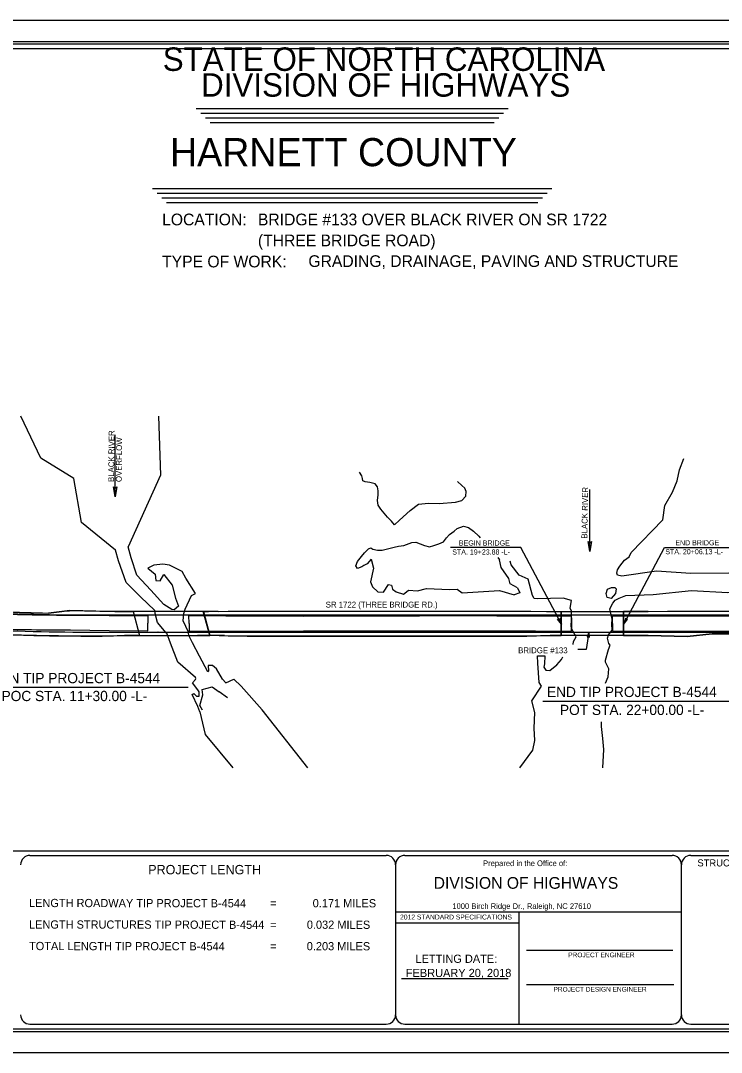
# Model space of a CAD drawing. Extents: x 0 to 2021, y 0 to 1321.
# Drawn here: x 675 to 1572, y 0 to 1321 of the extents above; entities that cross this region are included whole.
import ezdxf

# ---------------------------------------------------------------- set-up
doc = ezdxf.new("R2010")
doc.units = 0
for name, color, linetype in [('Arrowhead Terminators CELL', 7, 'Continuous'), ('Default', 7, 'Continuous'), ('Dimension Lines', 7, 'Continuous'), ('Exist Hydro Stream or Body of Water', 7, 'Continuous'), ('Exist Roads EOP', 7, 'Continuous'), ('Prop EOT', 7, 'Continuous'), ('Sheet Data Field CELL', 7, 'Continuous'), ('Sheet Plot Border Inside CELL', 7, 'Continuous'), ('Sheet Plot Border Outside CELL', 7, 'Continuous'), ('Sheet Title CELL', 7, 'Continuous'), ('Text', 7, 'Continuous')]:
    doc.layers.add(name, color=color, linetype=linetype)

msp = doc.modelspace()

# ---------------------------------------------------------------- linework, layer by layer
at = {"layer": 'Arrowhead Terminators CELL'}
for points in [[(850.5, 537.9), (850.4, 537.9), (850.5, 537.9)], [(850.5, 537.9), (850.4, 537.8), (850.5, 537.8)], [(1402.2, 537.9), (1399.8, 532), (1402.8, 531.5)]]:
    msp.add_lwpolyline(points, close=True, dxfattribs=at)
at = {"layer": 'Default'}
for p, q in [((795.7, 711.1), (795.7, 790.4)), ((1403.5, 641.2), (1403.5, 720.4)), ((737.4, 565.4), (710.2, 562.3)), ((737.3, 565.4), (795.1, 564.4)), ((787.3, 564.4), (737.4, 565.4)), ((818.6, 564.4), (787.3, 564.4)), ((795.1, 564.4), (818.5, 564.4)), ((818.5, 564.4), (826.8, 533.5)), ((818.5, 564.4), (826.8, 533.5)), ((908.5, 564.4), (818.5, 564.4)), ((916.7, 533.5), (908.4, 564.4)), ((908.4, 564.4), (915.3, 564.4)), ((927.3, 564.4), (908.4, 564.4)), ((908.5, 564.4), (916.8, 533.5)), ((915.3, 564.4), (940.3, 564.9)), ((927.3, 564.4), (956.4, 564.9)), ((940.3, 564.9), (1327.8, 564.9)), ((956.4, 564.9), (1322.9, 564.9)), ((1322.9, 564.9), (1347.9, 564.4)), ((1327.8, 564.9), (1352.8, 564.4)), ((1347.9, 564.4), (1366.7, 564.4)), ((1352.8, 564.4), (1366.6, 564.4)), ((1366.6, 564.4), (1366.6, 533.5)), ((1366.6, 564.4), (1366.6, 533.5)), ((1477.9, 564.4), (1446.5, 564.4)), ((1446.6, 533.5), (1446.6, 564.4)), ((1446.6, 564.4), (1477.9, 564.4)), ((1477.9, 564.4), (1502.9, 564.9)), ((1477.9, 564.4), (1502.9, 564.9)), ((1502.9, 564.9), (1613.5, 564.9)), ((1502.9, 564.9), (1613.5, 564.9)), ((751.5, 532.9), (778.8, 532.9)), ((778.8, 532.9), (808, 533.5)), ((826.8, 533.5), (807.6, 533.5)), ((808, 533.5), (826.9, 533.5)), ((826.8, 533.5), (916.8, 533.5)), ((919.7, 533.5), (900.9, 533.5)), ((935.5, 533.5), (908.4, 533.5)), ((940.3, 532.9), (916.7, 533.5)), ((916.7, 533.5), (916.7, 533.5)), ((935.5, 533.5), (964.7, 532.9)), ((1327.8, 532.9), (940.3, 532.9)), ((964.7, 532.9), (1322.9, 532.9)), ((1322.9, 532.9), (1347.9, 533.5)), ((1352.8, 533.5), (1327.8, 532.9)), ((1347.9, 533.5), (1366.7, 533.5)), ((1366.6, 533.5), (1352.8, 533.5)), ((1446.5, 533.5), (1477.9, 533.5)), ((1477.9, 533.5), (1446.6, 533.5)), ((1527.9, 532.5), (1477.9, 533.5)), ((1477.9, 533.5), (1527.9, 532.5)), ((1559.9, 535.9), (1527.9, 532.5)), ((1527.9, 532.5), (1559.9, 535.9)), ((1641.6, 535.9), (1559.9, 535.9)), ((1559.9, 535.9), (1641.6, 535.9))]:
    msp.add_line(p, q, dxfattribs=at)
for points in [[(797.9, 723.7), (795.7, 711.1), (793.5, 723.8), (795.7, 722.2)], [(1405.7, 653.8), (1403.5, 641.2), (1401.3, 653.9), (1403.5, 652.3)], [(1364.5, 555.6), (1367, 547.9), (1362, 554.3), (1363.7, 554.1)], [(1449.3, 555.6), (1446.8, 547.9), (1451.8, 554.3), (1450.1, 554.1)]]:
    msp.add_lwpolyline(points, close=True, dxfattribs=at)
for centre, radius, start, end in [((733.6, 2481.6), 1919.4, 265.7307, 269.2997), ((751.5, 2891), 2329, 266.0471, 268.9838), ((-31.9, 7212.3), 6691.3, 276.36675, 276.6009), ((751.5, 2891), 2358, 267.4051, 270), ((760.5, 3797.9), 3264.7, 268.1837, 270.8273)]:
    msp.add_arc(centre, radius, start, end, dxfattribs=at)
at = {"layer": 'Dimension Lines'}
for p, q in [((1314.9, 646.3), (1225.1, 646.3)), ((1367, 547.9), (1314.9, 646.3)), ((1446.8, 547.9), (1498.9, 646.3)), ((1498.9, 646.3), (1581.8, 646.3)), ((1402.2, 537.9), (1398.8, 515.7)), ((1398.8, 515.7), (1388.2, 515.7)), ((889.2, 467.2), (610.1, 467.1)), ((1608.3, 449.3), (1343, 449.3))]:
    msp.add_line(p, q, dxfattribs=at)
at = {"layer": 'Exist Hydro Stream or Body of Water'}
msp.add_line((939.4, 453.7), (928.8, 461.4), dxfattribs=at)
for points in [[(796.1, 642.8), (752.5, 678.1), (742.6, 734.4), (700.4, 760.6), (674.8, 814.4)], [(851, 814.4), (853.8, 738.9), (812.4, 647)], [(1456.1, 639.7), (1496.7, 681.5), (1499.6, 700.1), (1509.4, 717), (1515.3, 731.6), (1518.4, 745.6), (1523.7, 760)], [(1153.3, 675.1), (1149.5, 679.8), (1144.5, 685), (1139.9, 690.3), (1135.8, 695.5), (1132.5, 700.6), (1131.5, 706.3), (1132.2, 713.5), (1132.3, 718.7), (1131.3, 724), (1128.4, 727.8), (1121.8, 729.4), (1115.9, 730.4), (1112.6, 731.4), (1112.1, 734.6), (1111.6, 738.1), (1108.5, 742.6)], [(1153.3, 675.1), (1159.7, 681.3), (1173.2, 693.8), (1183.9, 701.7), (1196.6, 702.8), (1210.6, 702.7), (1231.4, 704.4), (1239.6, 706.4), (1244.8, 711.9), (1245.2, 717.8), (1243.2, 722.1), (1239.4, 725.5), (1233.8, 730.8)], [(1153, 646.5), (1158.2, 648.1), (1165, 648.8), (1175.3, 652.6), (1180.4, 653.1), (1186.1, 651.1), (1191.7, 648.9), (1198.1, 647.3), (1203.8, 648.6), (1209.9, 651), (1215.8, 653.7), (1219.7, 658.8), (1223.8, 662.9), (1229.6, 667.2), (1233.3, 670.6), (1241.7, 673.5), (1248, 672), (1254.6, 667.2), (1261.3, 660.9), (1263, 658.7)], [(901.4, 464.1), (894.5, 472.8), (898.3, 477.3), (898.7, 478.7), (898.5, 480), (876, 499.6), (866.6, 523.8), (861.8, 536.7), (860.7, 536.8), (849.8, 550.1), (846.9, 561.6), (846.4, 565.6), (828, 583.3), (809.5, 601.6), (799.8, 629), (796.1, 642.8)], [(933, 477.5), (925.3, 490.8), (920.2, 495.3), (914.6, 495), (915.3, 487.9), (914.2, 487.1), (903.4, 507), (894.6, 524.3), (890.5, 532.6), (889.7, 532.7), (889.6, 537.7), (882.8, 552.4), (883.3, 561.9), (885.4, 567.2), (893.2, 584.8), (898.3, 587.5), (886.1, 607), (881.5, 615.6), (865, 623.5), (856.7, 624.7), (845, 623.8), (837.5, 619.6), (846.7, 611.9), (847.8, 603.9), (853, 603.4), (858.1, 611.5), (868.7, 598), (873, 581.2), (876.8, 571.1), (871.3, 566.3), (868.3, 566.8), (858.1, 573.4), (841.3, 591.5), (823.5, 610.7), (816.1, 633), (812.4, 647)], [(1123.3, 631.5), (1118.1, 625.4), (1114.1, 623.3), (1111.3, 621.7), (1105.9, 619.5), (1103.8, 622.7), (1105.8, 628.5), (1110.9, 634.8), (1114.9, 639.2), (1120.1, 644.5), (1123.1, 645.6), (1125.5, 644), (1131.3, 642.8), (1137.6, 642.9), (1140.9, 643.7), (1153, 646.5)], [(1429, 567.6), (1432.9, 575), (1436, 578.9), (1440.9, 581.2), (1449.4, 584.6), (1484.6, 586.2), (1533.6, 591.4), (1580.2, 588.6), (1635.2, 593.2), (1676.5, 589.5), (1680.5, 586.7), (1684, 583.8), (1733, 580.8), (1774.3, 583), (1774.8, 584.4), (1773.2, 593), (1775.8, 594.6), (1772.2, 601.2), (1772.2, 604.6), (1776.1, 613.6), (1836.6, 639), (1842.3, 644.3)], [(1636.7, 612.3), (1580.5, 613.2), (1532.6, 613), (1488.7, 616.1), (1444.2, 609.6), (1438.9, 610.9), (1437.9, 613.4), (1439, 617.7), (1441.7, 622.4), (1447.6, 630.2), (1453.7, 634.4), (1456.1, 639.7)], [(1123.3, 631.5), (1126.4, 619.7), (1122.5, 602.4), (1125.2, 595.9), (1131.9, 589.6), (1139.1, 589.2), (1145.5, 598.7), (1149.5, 598), (1150.5, 592.7), (1155.3, 589.7), (1164.6, 586.4), (1168.6, 589.4), (1171.2, 591.7), (1182.8, 590.9), (1194.3, 593.9), (1223.6, 592.6), (1233.6, 592.9), (1239.8, 588.3), (1287.8, 591), (1306.6, 585.8)], [(1285.6, 633.5), (1287.9, 630.5)], [(1310.9, 594.8), (1301.2, 599.6), (1299.7, 606.7), (1289.9, 620.8), (1287.9, 630.5)], [(1382.6, 525.9), (1386, 531.8), (1380.2, 541.8), (1380.2, 547.9), (1380.1, 564.9), (1379.7, 564.8), (1378.1, 568.5), (1379.8, 578.6), (1369.3, 581.5), (1336.6, 580.6), (1332, 581), (1330, 584.9), (1324.5, 605.9), (1312.7, 610.9), (1302.7, 623.9), (1301.2, 628.8)], [(1310.9, 594.8), (1313.6, 588.2), (1306.6, 585.8)], [(1431.1, 595), (1435.5, 595.2), (1437.3, 593.5), (1436.2, 587.2), (1430.7, 581), (1425.7, 582.3), (1424.1, 587.2), (1426, 592.7), (1431.1, 595)], [(1427.2, 534.3), (1431.8, 540.4), (1431.7, 548), (1431.8, 554.3), (1429, 567.6)], [(1432.3, 559.6), (1432.3, 559.6)], [(1423.3, 472.6), (1427, 480.9), (1427.9, 490.9), (1423.3, 499.5), (1423.3, 502.1), (1427.4, 515.6), (1429.5, 521.1), (1427.7, 523.4), (1425.9, 530.1), (1427.2, 534.3)], [(1381.9, 521.9), (1382.6, 525.9)], [(1341.6, 468.7), (1338.5, 473.6), (1337, 498), (1336.4, 507.6), (1345.6, 507.4), (1345.2, 497.3), (1344.6, 492.9), (1347.1, 489.4), (1352, 488.6), (1361.2, 496), (1367.3, 502.8), (1368.7, 506.4)], [(933, 477.5), (937.2, 473), (947.6, 477.8), (957, 468.7)], [(904, 435.8), (901.3, 442.8), (894.1, 458.1), (896.5, 459.2), (899.9, 455.8), (903.3, 455.8), (903.3, 461.6), (901.4, 464.1)], [(907.3, 437.9), (903.9, 443.8), (907.7, 457.6), (906.8, 464.3), (920, 468.1), (928.8, 461.4)], [(1042.2, 364.4), (984, 438.3), (957, 468.7)], [(1330.2, 387), (1333.1, 399.3), (1332.3, 414.9), (1333.1, 435.2), (1329.1, 449.8), (1341.6, 468.7)], [(904, 435.8), (910.9, 406.8), (946.2, 364.4)], [(1418, 423.2), (1418.1, 416.9), (1419.7, 401.8), (1420.8, 387.8), (1419.7, 364.4)], [(1313.7, 364.4), (1330.2, 387)]]:
    msp.add_lwpolyline(points, dxfattribs=at)
at = {"layer": 'Exist Roads EOP'}
for points in [[(739.1, 559.7), (739.1, 559.7), (788, 559.4), (837.2, 559.4), (837.4, 549.5)], [(890.2, 549.1), (890.1, 559.1), (937.1, 558.7), (986.9, 558.7), (1036.8, 558.5), (1086.3, 558.7), (1135.8, 558.8), (1185.4, 558.9), (1235.2, 559), (1284.5, 558.8), (1334.1, 558.6), (1379.6, 558.7), (1379.6, 549.2)], [(890.2, 549.1), (890.1, 559.1), (937.1, 558.7), (986.9, 558.7), (1036.8, 558.5), (1086.3, 558.7), (1135.8, 558.8), (1185.4, 558.9), (1235.2, 559), (1284.5, 558.8), (1334.1, 558.6), (1379.6, 558.7), (1379.6, 549.2)], [(1432.3, 549), (1432.3, 558.5), (1483.3, 558.8), (1532.5, 558.6), (1582.3, 558.5), (1632.3, 558.5), (1681.9, 558.6), (1731.9, 558.3), (1780.9, 558.3), (1831, 558.5), (1880.4, 558.8), (1894, 558.8)], [(738.2, 540.8), (738.2, 540.8), (787.7, 540.1), (837.5, 539.5), (837.4, 549.5)], [(890.2, 549.1), (890.3, 539.3), (937.3, 539.1), (987.3, 539.2), (1036.7, 539.5), (1086.3, 539.6), (1135.6, 539.7), (1185.3, 539.6), (1234.8, 539.7), (1284.1, 539.6), (1333.9, 539.4), (1379.7, 539), (1379.6, 549.2)], [(1432.3, 549), (1432.2, 539.3), (1483, 539.2), (1532.5, 539), (1582.6, 539.1), (1632.1, 539.3), (1681.7, 539.5), (1731.7, 539.5), (1781.1, 539.4), (1830.8, 539.3), (1880.3, 539.8), (1894, 539.9)]]:
    msp.add_lwpolyline(points, dxfattribs=at)
for points in [[(378.9, 598.8), (397.3, 594.1), (445, 583.4), (493.3, 574.8), (542, 568.5), (590.7, 564.1), (639.8, 561.6), (689.2, 560.2), (739.1, 559.7)], [(378.9, 578.8), (392.7, 575.2), (441.2, 564.2), (490.5, 555.9), (540, 549.2), (589.4, 544.9), (639, 542.3), (688.6, 541.1), (738.2, 540.8)]]:
    msp.add_spline(points, degree=3, dxfattribs=at)
at = {"layer": 'Prop EOT'}
for p, q in [((751.5, 559.9), (1641.6, 559.9)), ((751.5, 537.9), (1641.6, 537.9))]:
    msp.add_line(p, q, dxfattribs=at)
for radius in [2331, 2353]:
    msp.add_arc((751.5, 2891), radius, 266.0471, 270, dxfattribs=at)
at = {"layer": 'Sheet Plot Border Inside CELL'}
msp.add_lwpolyline([(15.6, 26.9), (2015.8, 26.9), (2015.8, 1293.7), (15.6, 1293.7)], close=True, dxfattribs=at)
at = {"layer": 'Sheet Plot Border Outside CELL'}
msp.add_lwpolyline([(2021.2, 1320.6), (0, 1320.6), (0, 0), (2021.2, 0)], close=True, dxfattribs=at)
at = {"layer": 'Sheet Title CELL'}
for p, q in [((899.4, 1208.3), (1298.8, 1208.3)), ((905.4, 1202.3), (1292.8, 1202.3)), ((911.4, 1196.3), (1286.8, 1196.3)), ((917.4, 1190.3), (1280.8, 1190.3)), ((843.5, 1105.9), (1354.7, 1105.9)), ((849.5, 1099.9), (1348.7, 1099.9)), ((855.5, 1093.9), (1342.7, 1093.9)), ((861.5, 1087.9), (1336.7, 1087.9)), ((278.5, 258.1), (1982.8, 258.1)), ((686.5, 252.1), (1142.6, 252.1)), ((1166.6, 252.1), (1508.7, 252.1)), ((1532.7, 252.1), (1772.4, 252.1)), ((1154.6, 240.1), (1154.6, 48)), ((1520.7, 48), (1520.7, 240.1)), ((1520.7, 179.6), (1154.6, 179.6)), ((1312.5, 179.6), (1312.5, 36)), ((1312.5, 165.5), (1154.6, 165.5)), ((1267, 171.1), (1267, 171.1)), ((1322.2, 130.8), (1509.8, 130.8)), ((1237, 113.6), (1237, 113.6)), ((1298.8, 94.3), (1162.2, 94.3)), ((1322.2, 86.9), (1511.1, 86.9))]:
    msp.add_line(p, q, dxfattribs=at)
for points in [[(1988.8, 1290.6), (212.4, 1290.6)], [(1982.8, 1284.6), (278.5, 1284.6)], [(212.4, 30), (1988.8, 30)], [(686.5, 36), (1142.6, 36)], [(1166.6, 36), (1508.7, 36)], [(1532.7, 36), (1772.5, 36)]]:
    msp.add_lwpolyline(points, dxfattribs=at)
for centre, major_axis, start_param, end_param in [((686.5, 240.2), (0, 12), 0, 1.570796), ((1142.6, 240.2), (0, 12), 4.712389, 6.283185), ((1166.6, 240.2), (0, 12), 0, 1.570796), ((1508.7, 240.2), (0, 12), 4.712389, 6.283185), ((1532.7, 240.2), (0, 12), 0, 1.570796), ((686.5, 48.1), (0, -12), 4.712389, 6.283185), ((1142.6, 48.1), (0, -12), 0, 1.570796), ((1166.6, 48.1), (0, -12), 4.712389, 6.283185), ((1508.7, 48.1), (0, 12), 3.141593, 4.712389), ((1532.7, 48.1), (0, -12), 4.712389, 6.283185)]:
    msp.add_ellipse(centre, major_axis=major_axis, ratio=0.999692, start_param=start_param, end_param=end_param, dxfattribs=at)
at = {"layer": 'Text'}
for p, q in [((1366.6, 533.5), (1366.6, 564.4)), ((1366.6, 564.4), (1446.6, 564.4)), ((1446.6, 564.4), (1446.6, 533.5)), ((1446.6, 533.5), (1366.6, 533.5))]:
    msp.add_line(p, q, dxfattribs=at)

# ---------------------------------------------------------------- texts
at = {"layer": 'Sheet Data Field CELL'}
for s, height, p in [('HARNETT COUNTY', 36.018, (865.7, 1134.3)), ('FEBRUARY 20, 2018', 10.505, (1167.8, 96.4))]:
    msp.add_text(s, height=height, dxfattribs=at).set_placement(p)
for s, height, rotation, p in [('BRIDGE #133 OVER BLACK RIVER ON SR 1722', 15.007, 360, (978.4, 1058.6)), ('(THREE BRIDGE ROAD)', 15.007, 360, (978.4, 1031.8)), ('GRADING, DRAINAGE, PAVING AND STRUCTURE', 15.007, 360, (1043, 1005.3)), ('LENGTH ROADWAY TIP PROJECT B-4544', 10.505, 359.915, (685.3, 186)), ('=', 10.5, 359.915, (994, 185.8)), ('0.171 MILES', 10.505, 359.915, (1048.5, 185.7)), ('LENGTH STRUCTURES TIP PROJECT B-4544', 10.505, 359.915, (685.3, 158.5)), ('=', 10.5, 359.915, (994, 158.2)), ('0.032 MILES', 10.505, 359.915, (1041, 158.2)), ('TOTAL LENGTH TIP PROJECT B-4544', 10.505, 359.915, (685.3, 130.9)), ('=', 10.5, 359.915, (993.9, 130.7)), ('0.203 MILES', 10.505, 359.915, (1040.9, 130.7))]:
    msp.add_text(s, height=height, rotation=rotation, dxfattribs=at).set_placement(p)
at = {"layer": 'Sheet Title CELL'}
for s, height, p in [('STATE OF NORTH CAROLINA', 30.015, (856.5, 1256.3)), ('DIVISION OF HIGHWAYS', 30.015, (905.6, 1223.3)), ('PROJECT LENGTH', 12.005, (837.9, 227.9)), ('STRUCTURES MANAGEMENT UNIT', 9.004, (1541.1, 238)), ('DIVISION OF HIGHWAYS', 15.007, (1203.4, 209.4)), ('2012 STANDARD SPECIFICATIONS', 6.243, (1160.4, 170.1)), ('LETTING DATE:', 10.505, (1180.2, 114.6))]:
    msp.add_text(s, height=height, dxfattribs=at).set_placement(p)
for s, height, p in [('LOCATION: ', 15.01, (855.7, 1058.6)), ('TYPE OF WORK:', 15.007, (855.7, 1004.8)), ('Prepared in the Office of:', 7.258, (1266.7, 238.4)), ('1000 Birch Ridge Dr., Raleigh, NC 27610', 7.258, (1227.3, 183.6)), ('PROJECT ENGINEER', 6.048, (1375.8, 121.7)), ('PROJECT DESIGN ENGINEER', 6.048, (1356.9, 77.7))]:
    msp.add_text(s, height=height, rotation=360, dxfattribs=at).set_placement(p)
at = {"layer": 'Text'}
for s, height, rotation, p in [('BLACK RIVER', 7.472, 89.4041, (794.1, 730.1)), ('OVERFLOW', 7.47, 89.4041, (803.9, 730)), ('BLACK RIVER', 7.472, 89.0284, (1400.1, 657.6)), ('BEGIN BRIDGE', 6.538, 0.007, (1235.7, 648.7)), ('END BRIDGE', 6.54, 0.007, (1512.8, 649)), ('STA. 19+23.88 -L-', 6.538, 0.007, (1227.2, 637.2)), ('STA. 20+06.13 -L-', 6.538, 0.007, (1500, 637.6)), ('SR 1722 (THREE BRIDGE RD.) ', 7.472, 360, (1065.2, 569.4)), ('BEGIN TIP PROJECT B-4544', 13.119, 0.007, (618.3, 472.5)), ('POC STA. 11+30.00 -L-', 13.119, 0.007, (650.1, 449.6)), ('END TIP PROJECT B-4544', 13.119, 0.007, (1348.5, 454.8)), ('POT STA. 22+00.00 -L-', 13.119, 0.007, (1365.1, 431.8))]:
    msp.add_text(s, height=height, rotation=rotation, dxfattribs=at).set_placement(p)
msp.add_text('BRIDGE #133', height=7.472, dxfattribs=at).set_placement((1311.6, 510.9))

doc.saveas('drawing.dxf')
